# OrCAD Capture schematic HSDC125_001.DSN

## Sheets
1 P08:  TUSB3410: size B; title: TDP0604WQFNEVM, TUSB3410; rev: A.0; company: Texas Instruments, CIS/ICP; note: GAGGIA.DSN
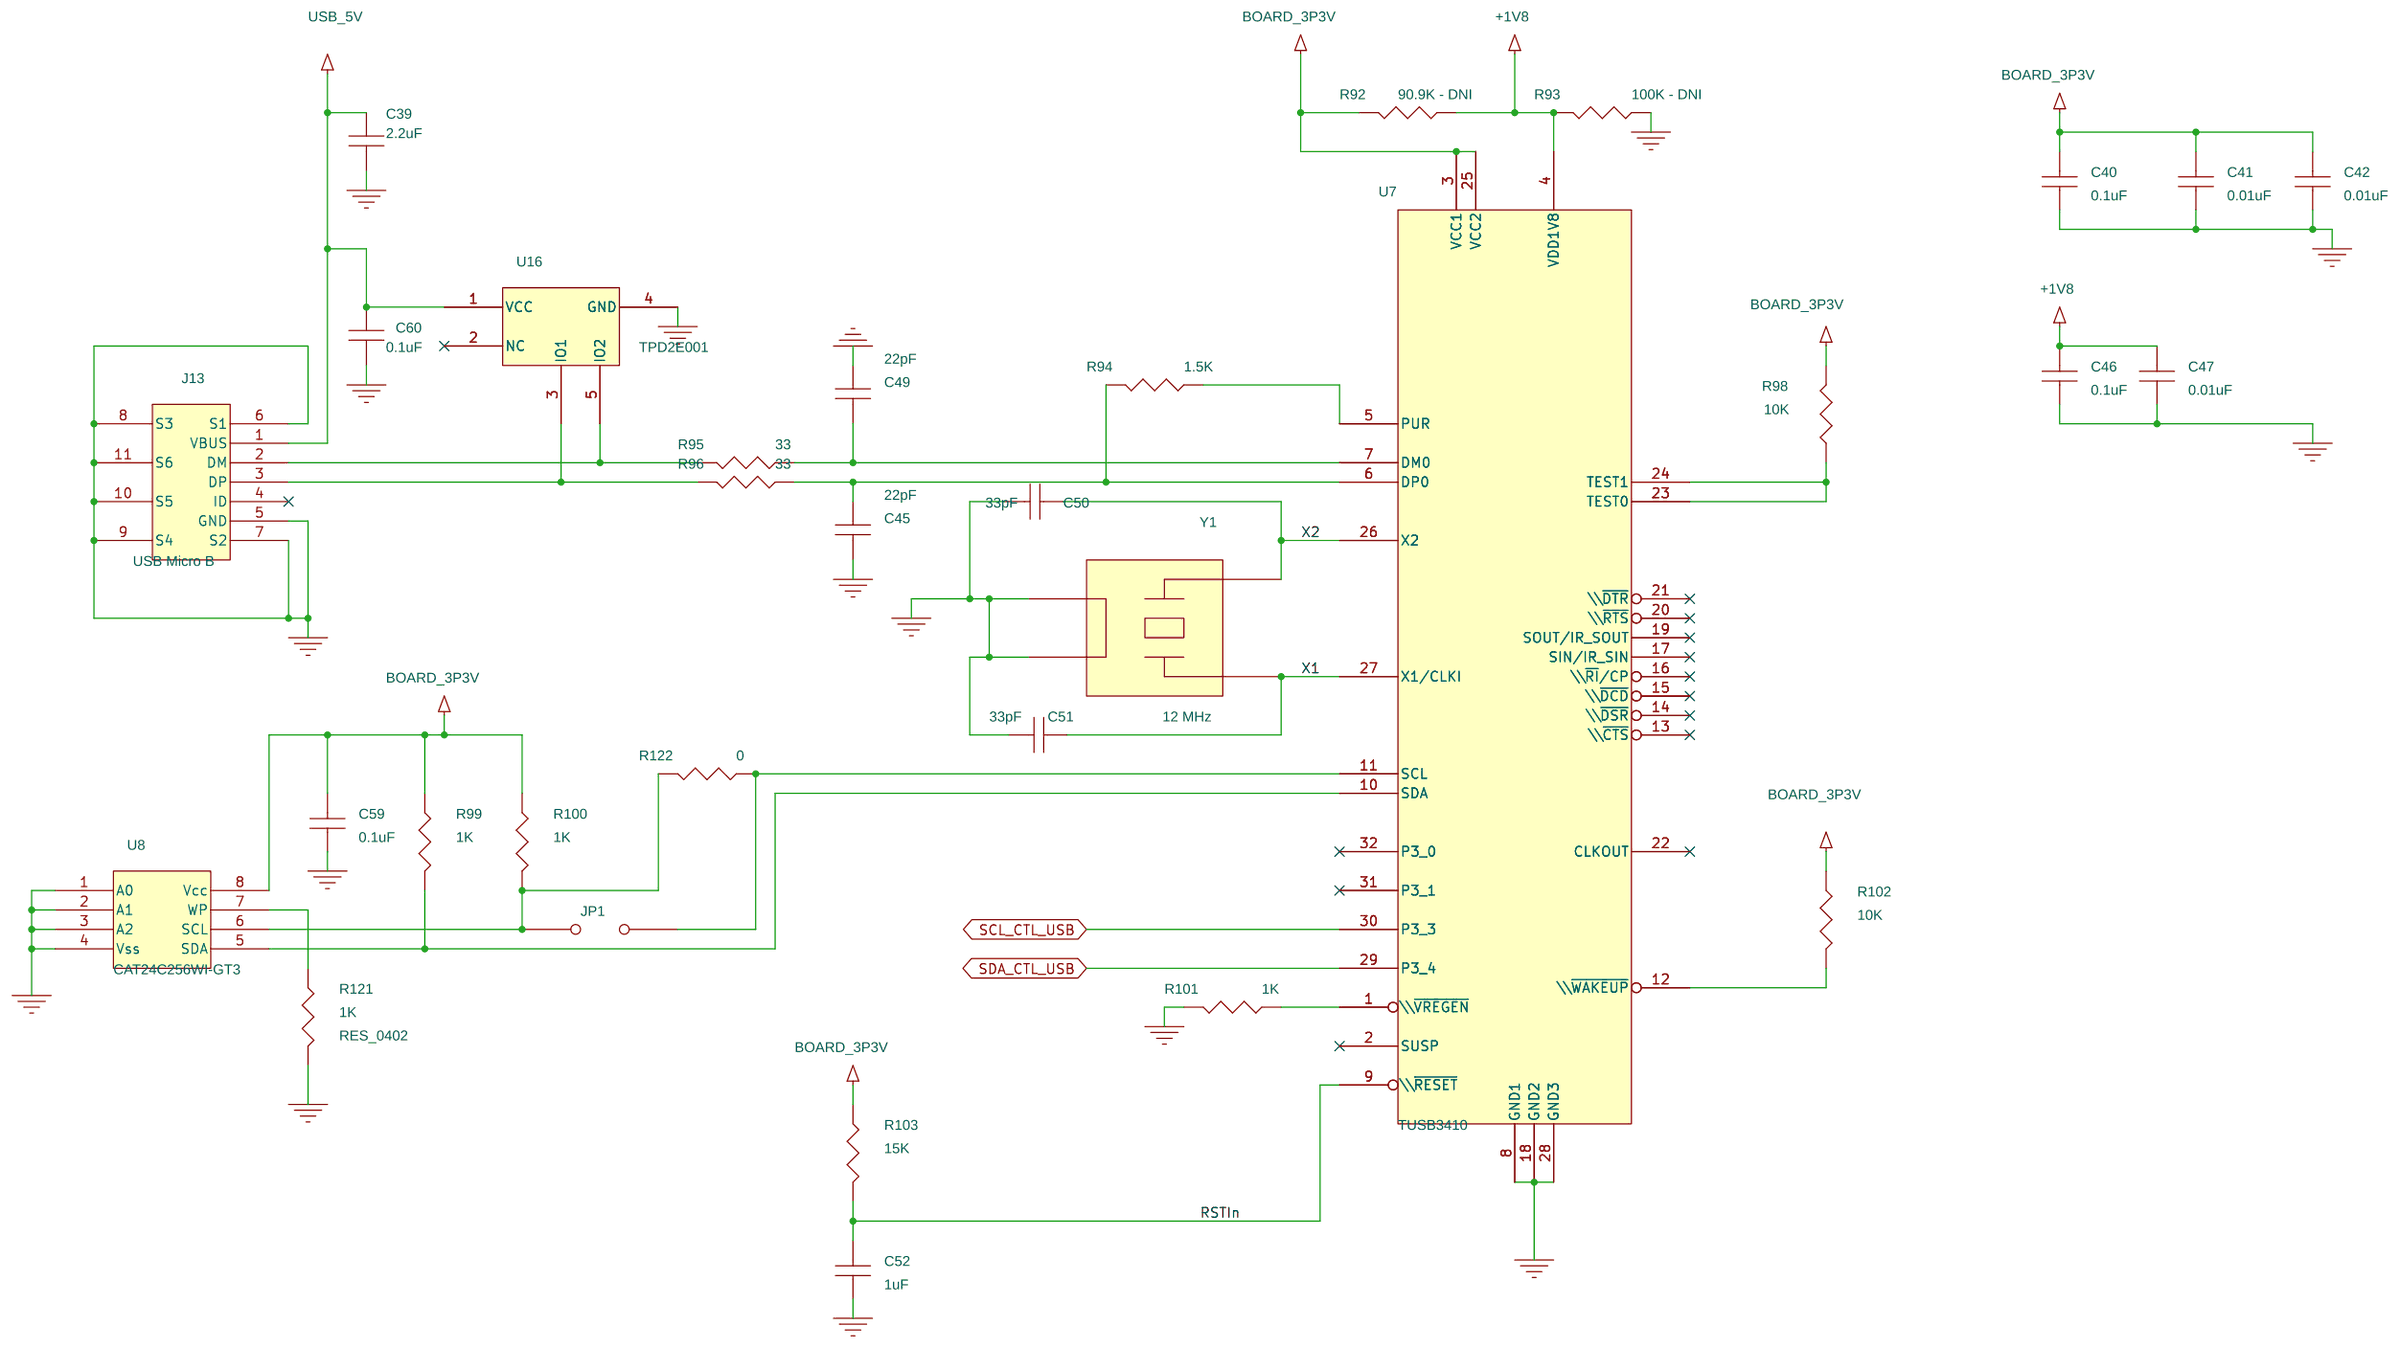
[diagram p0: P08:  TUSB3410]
2 P06:  RESET: size A; title: TDP0604WQFNEVM, RESET
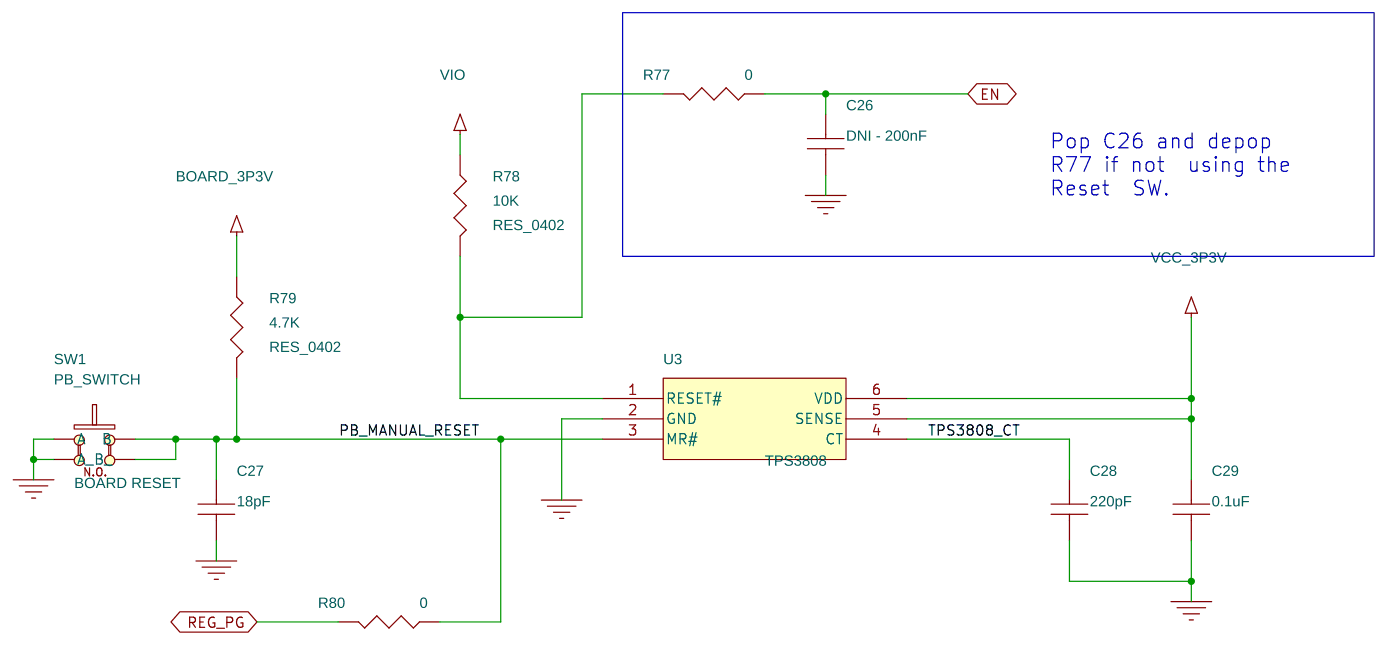
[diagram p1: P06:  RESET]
3 P01:  TITLE: title: TDP0604WQFNEVM, PROJECT# HSDC125_001
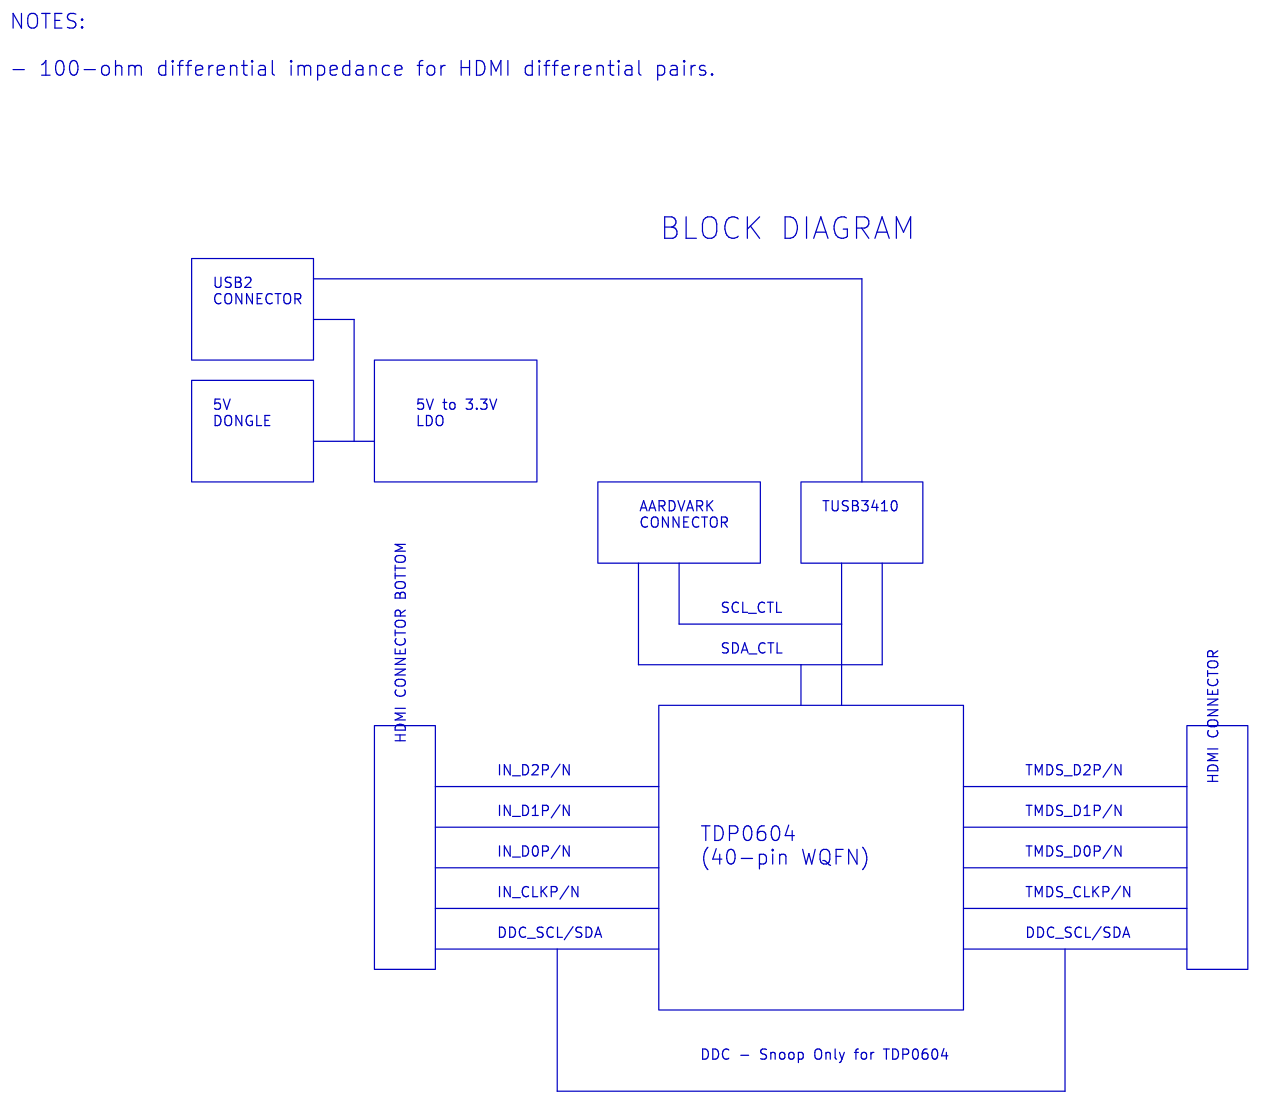
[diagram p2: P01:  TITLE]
4 P07:  POWER: size B; title: TDP0604WQFNEVM, REGULATORS
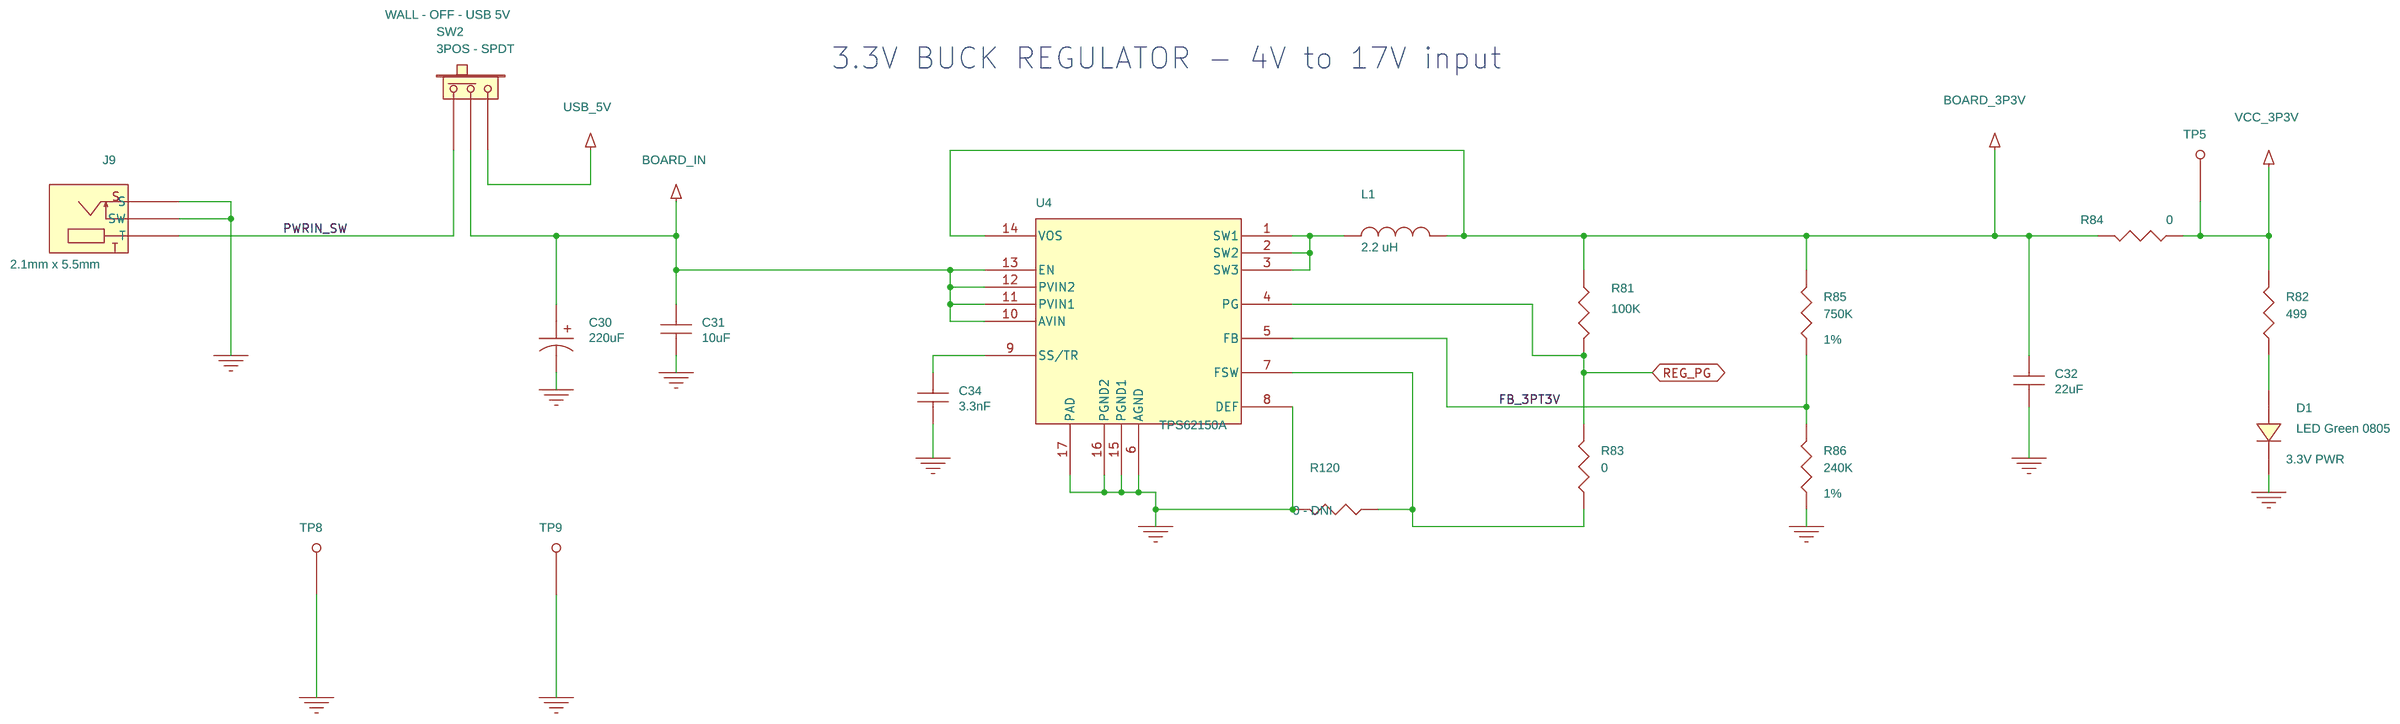
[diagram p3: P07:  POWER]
5 P03:  TDP0604WQFN: size B; title: TDP0604WQFNEVM, TDP0604 WQFN
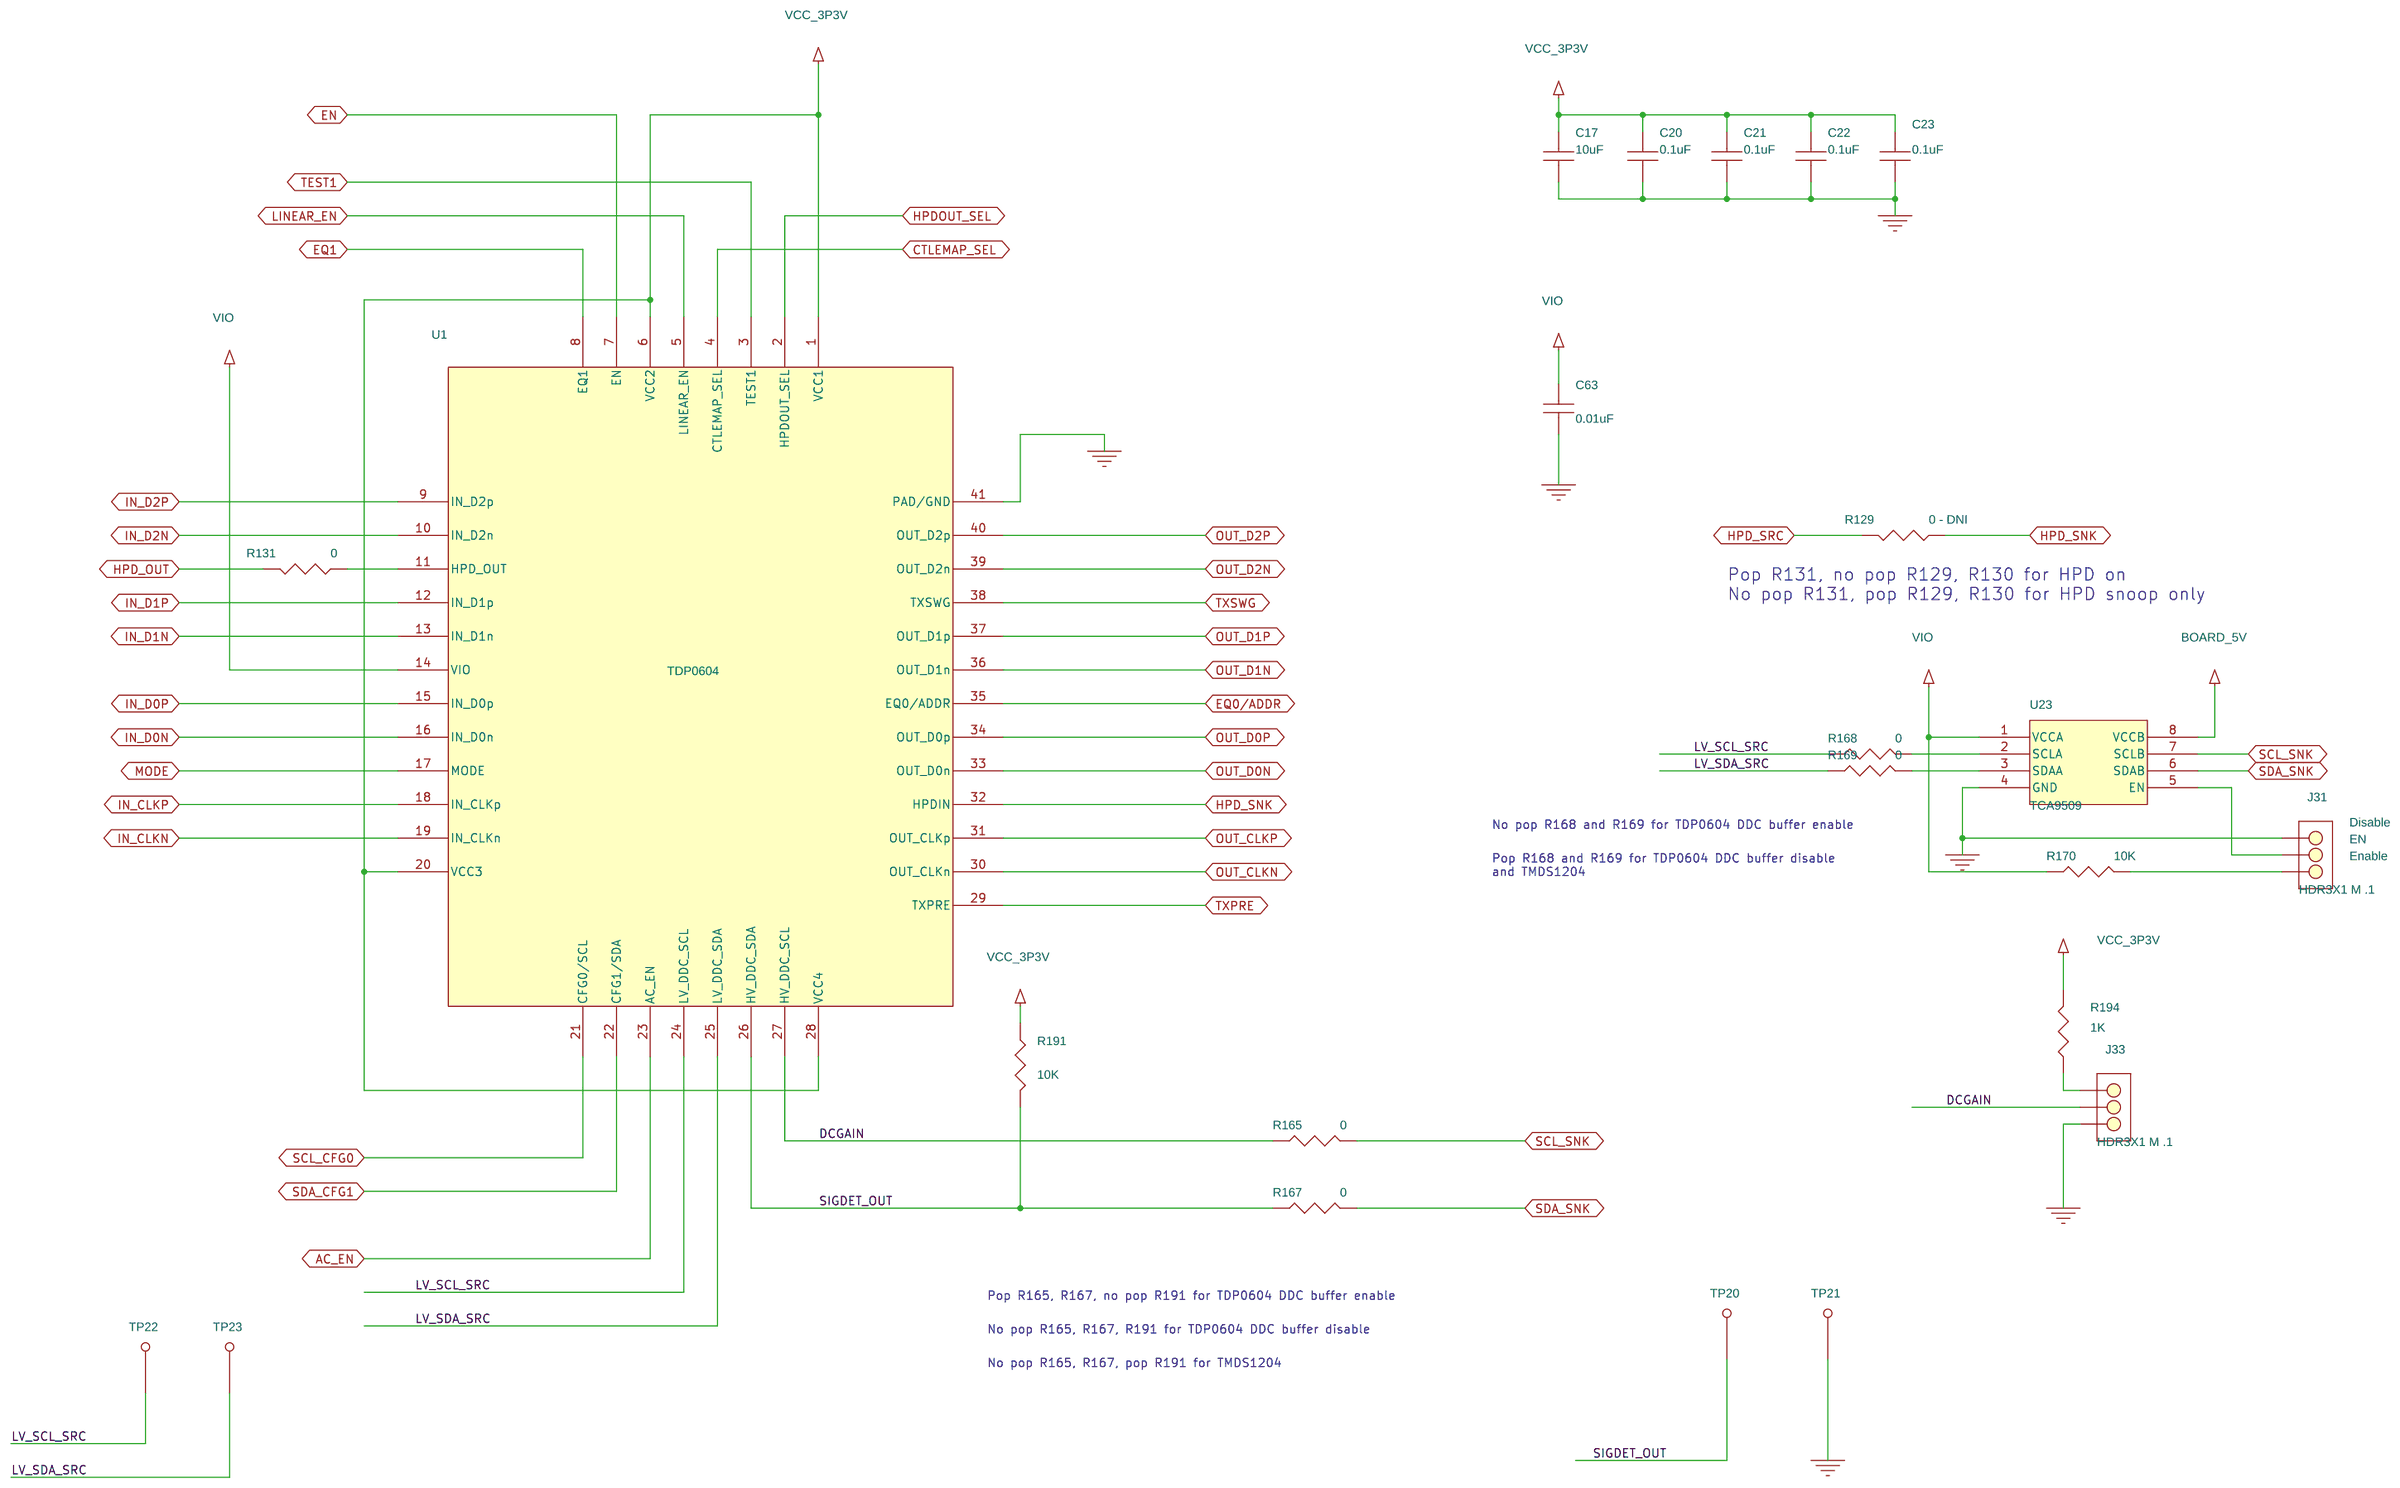
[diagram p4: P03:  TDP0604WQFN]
6 P09:  HARDWARE: title: TDP0604WQFNEVM, HARDWARE
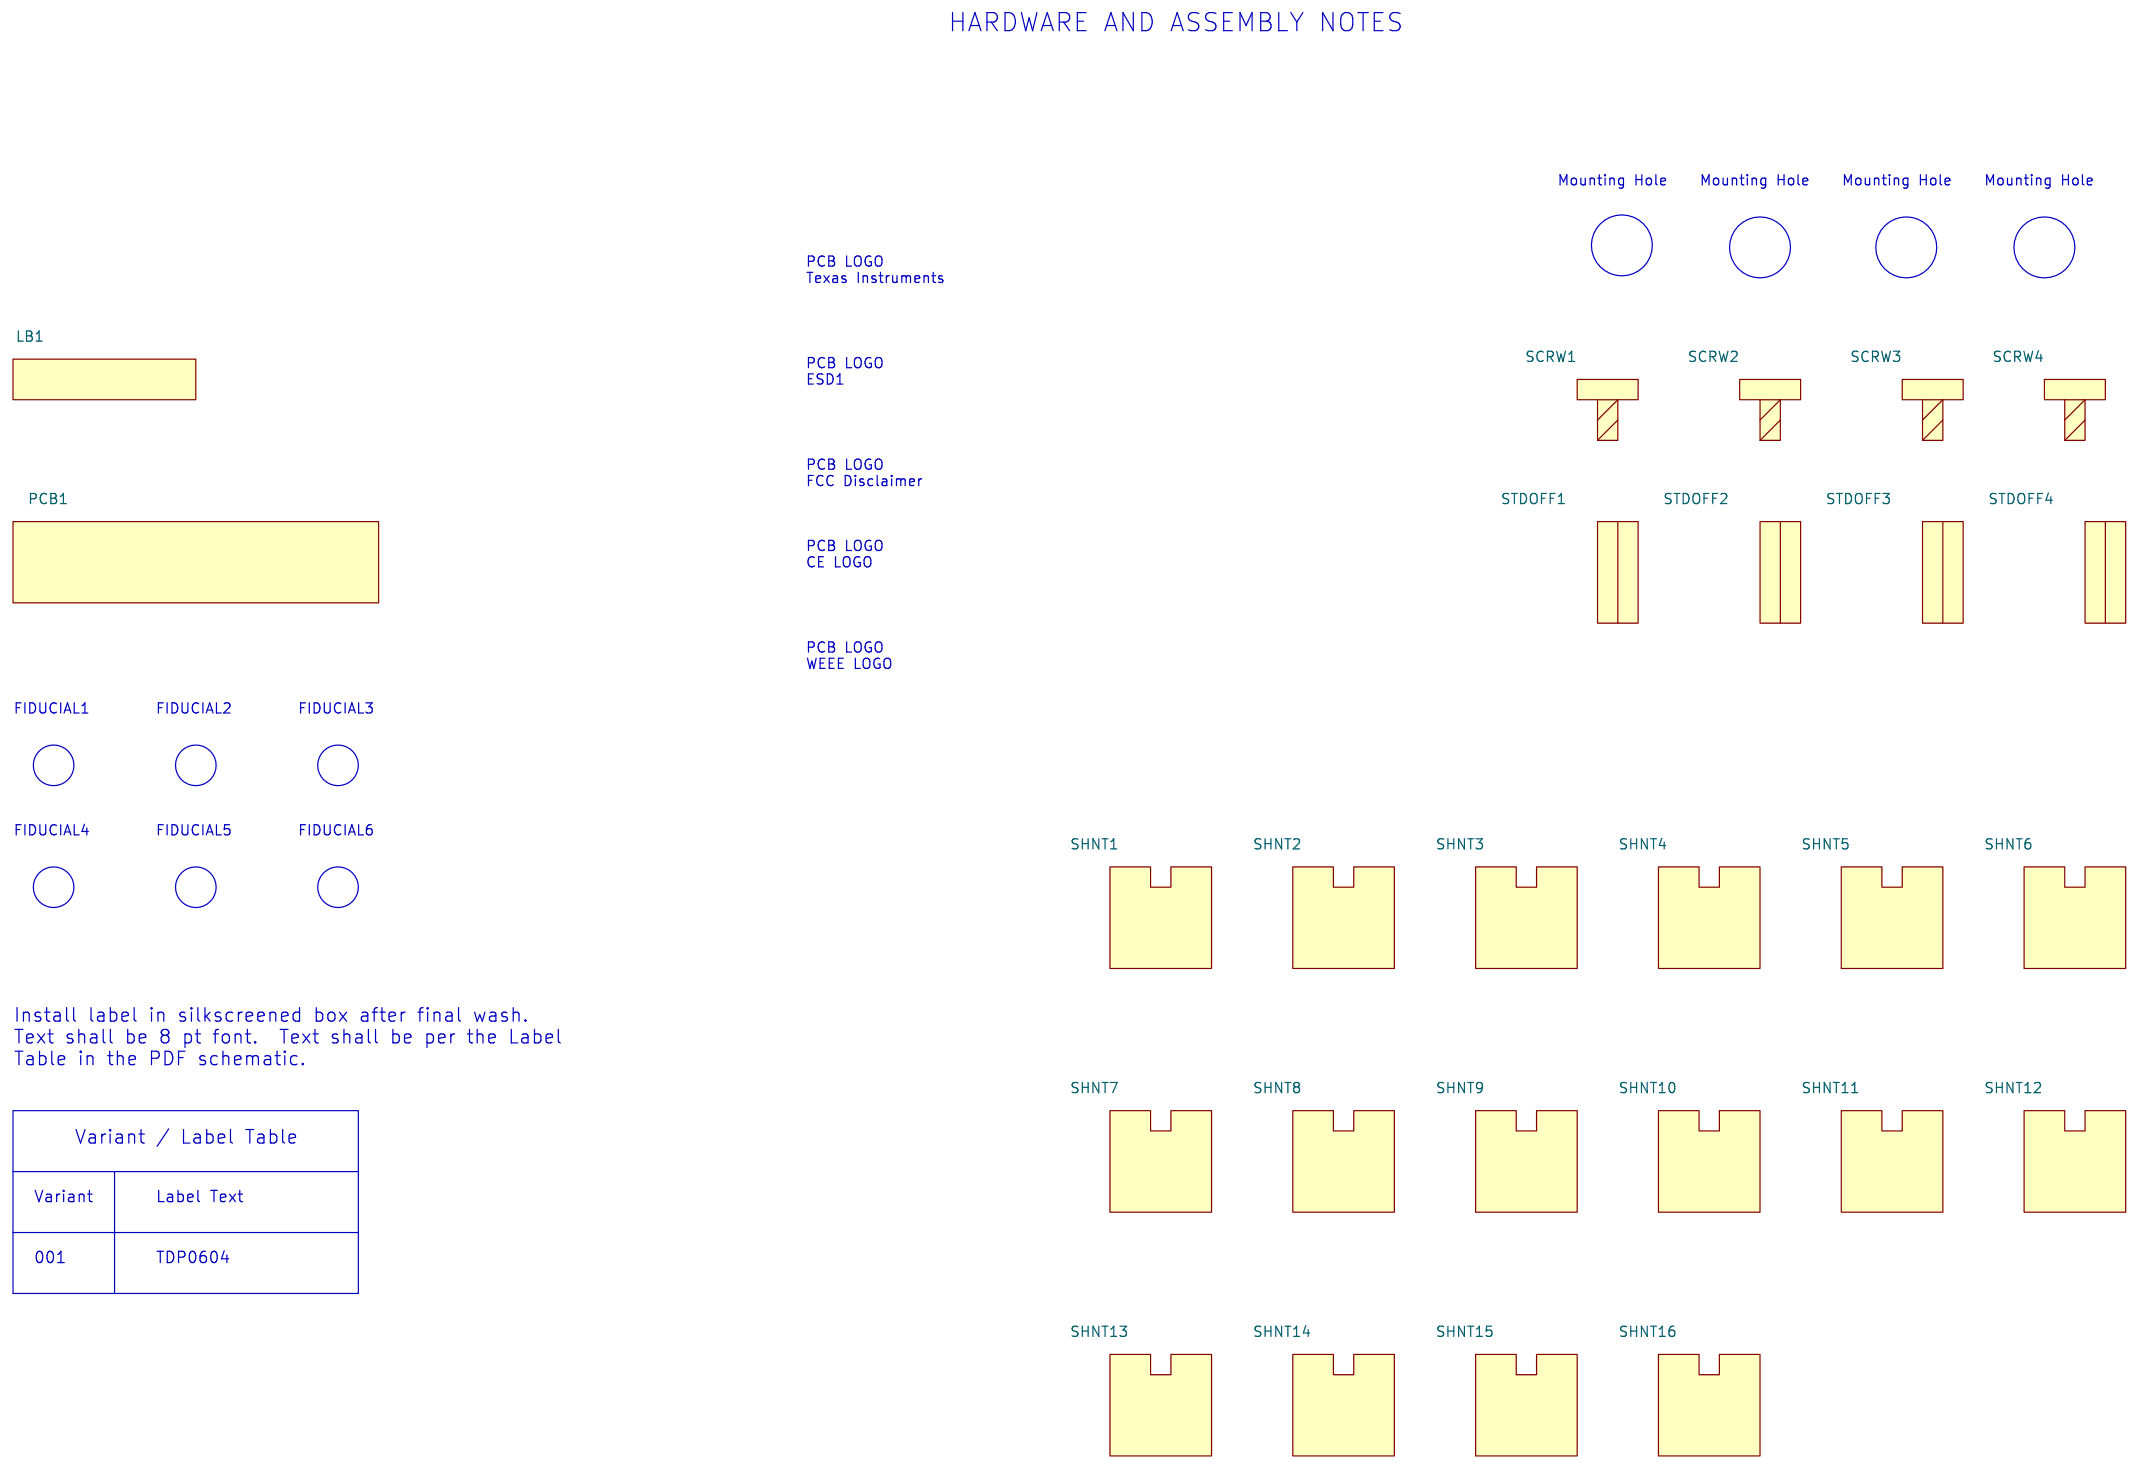
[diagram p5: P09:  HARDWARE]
7 P02:  HDMI INPUT CONNECTOR: size B; title: TDP0604WQFNEVM, HDMI INPUT
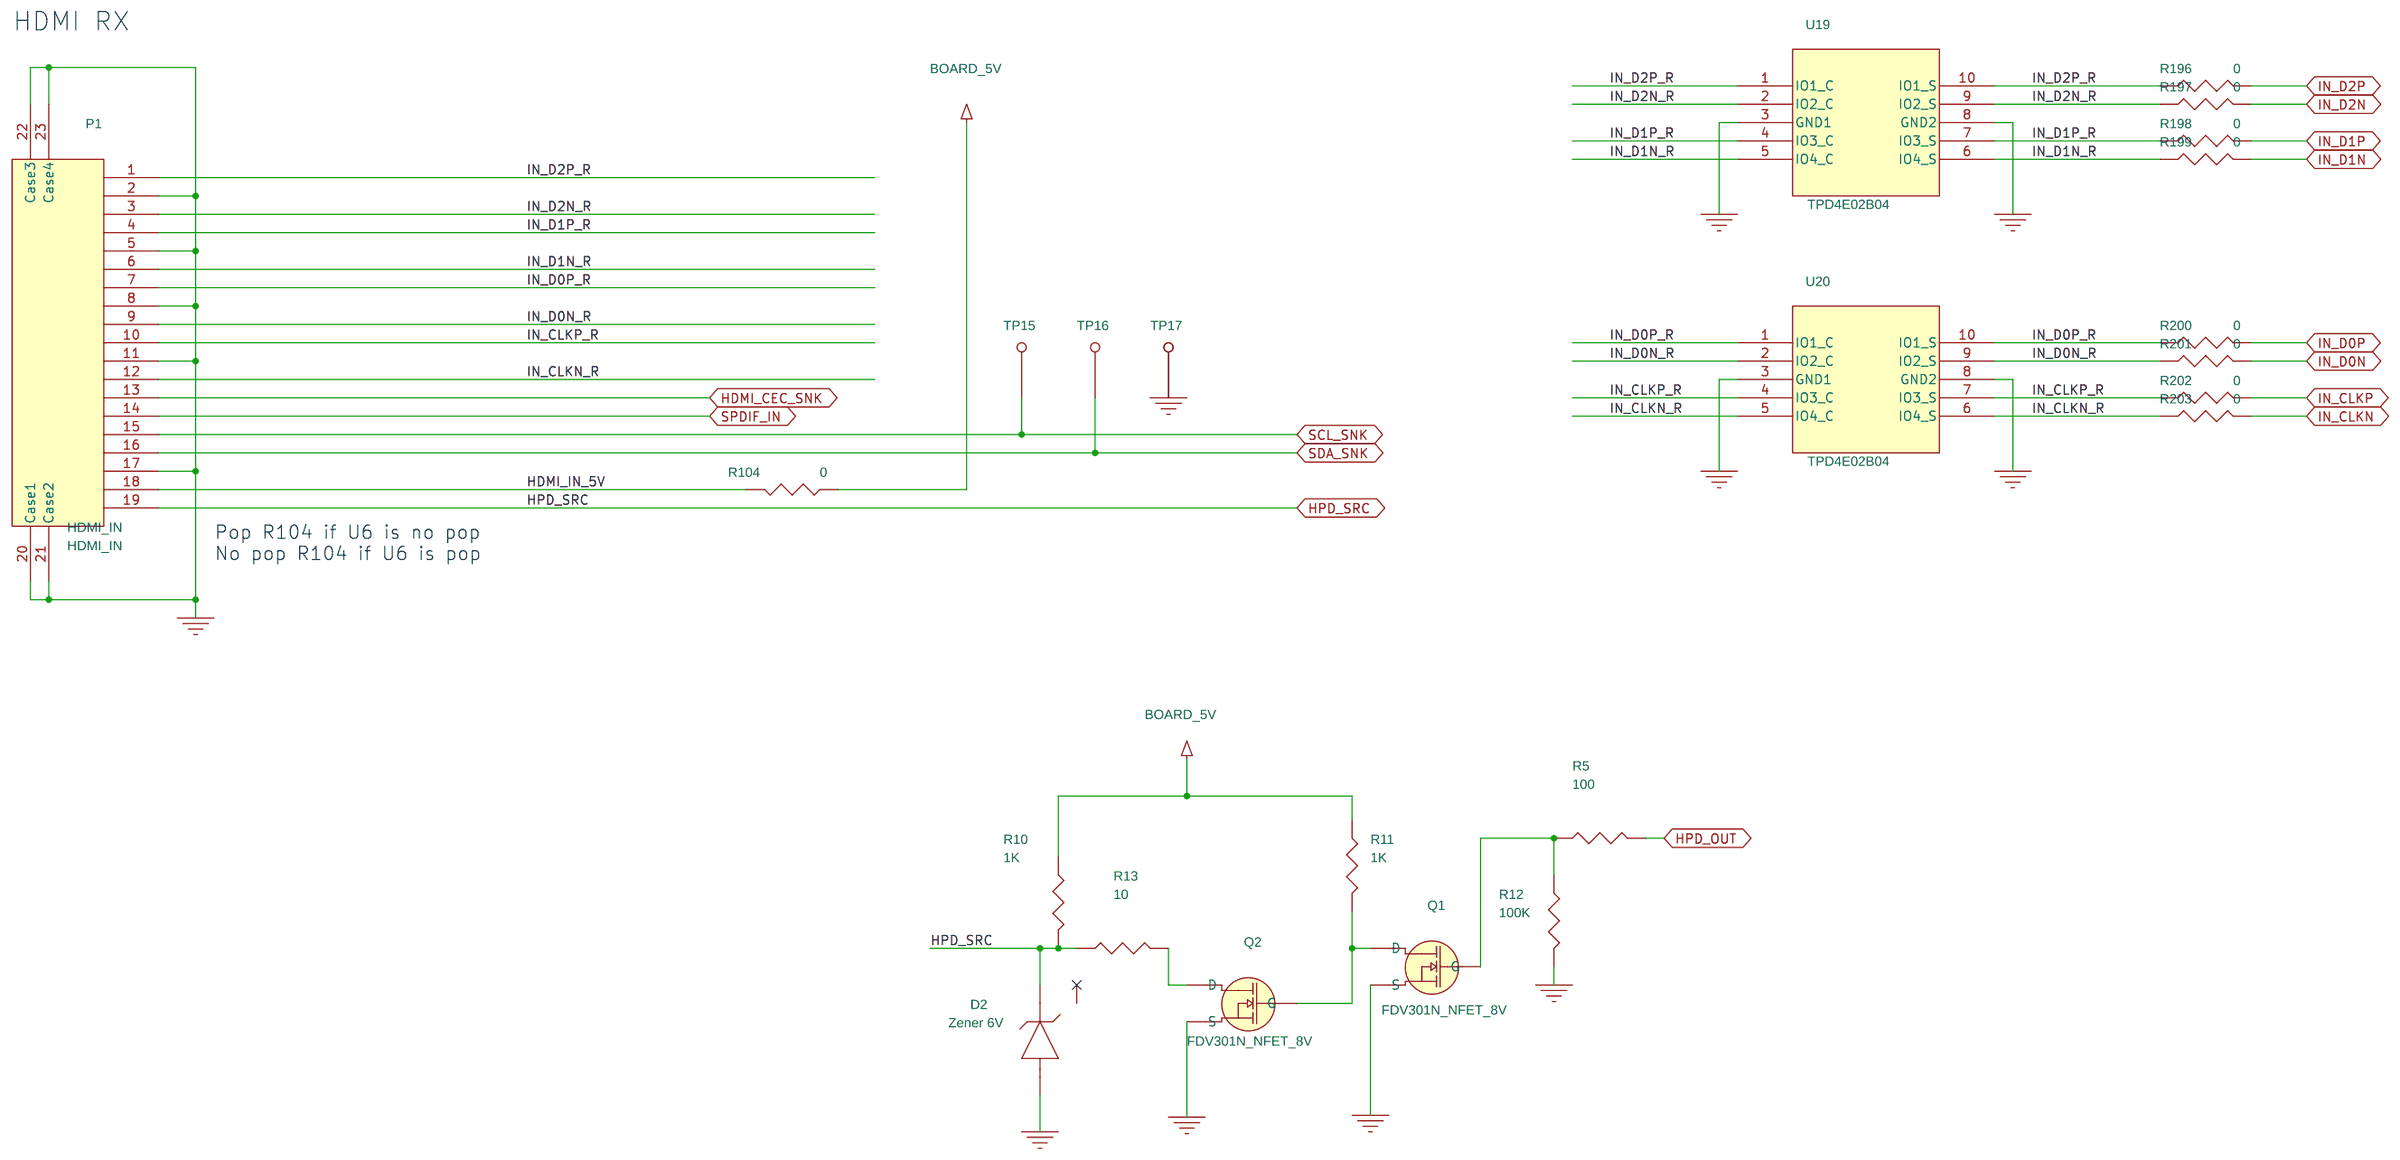
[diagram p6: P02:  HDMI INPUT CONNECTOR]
8 P04:  HDMI TX CONNECTOR: size B; title: TDP0604WQFNEVM, HDMI OUTPUT
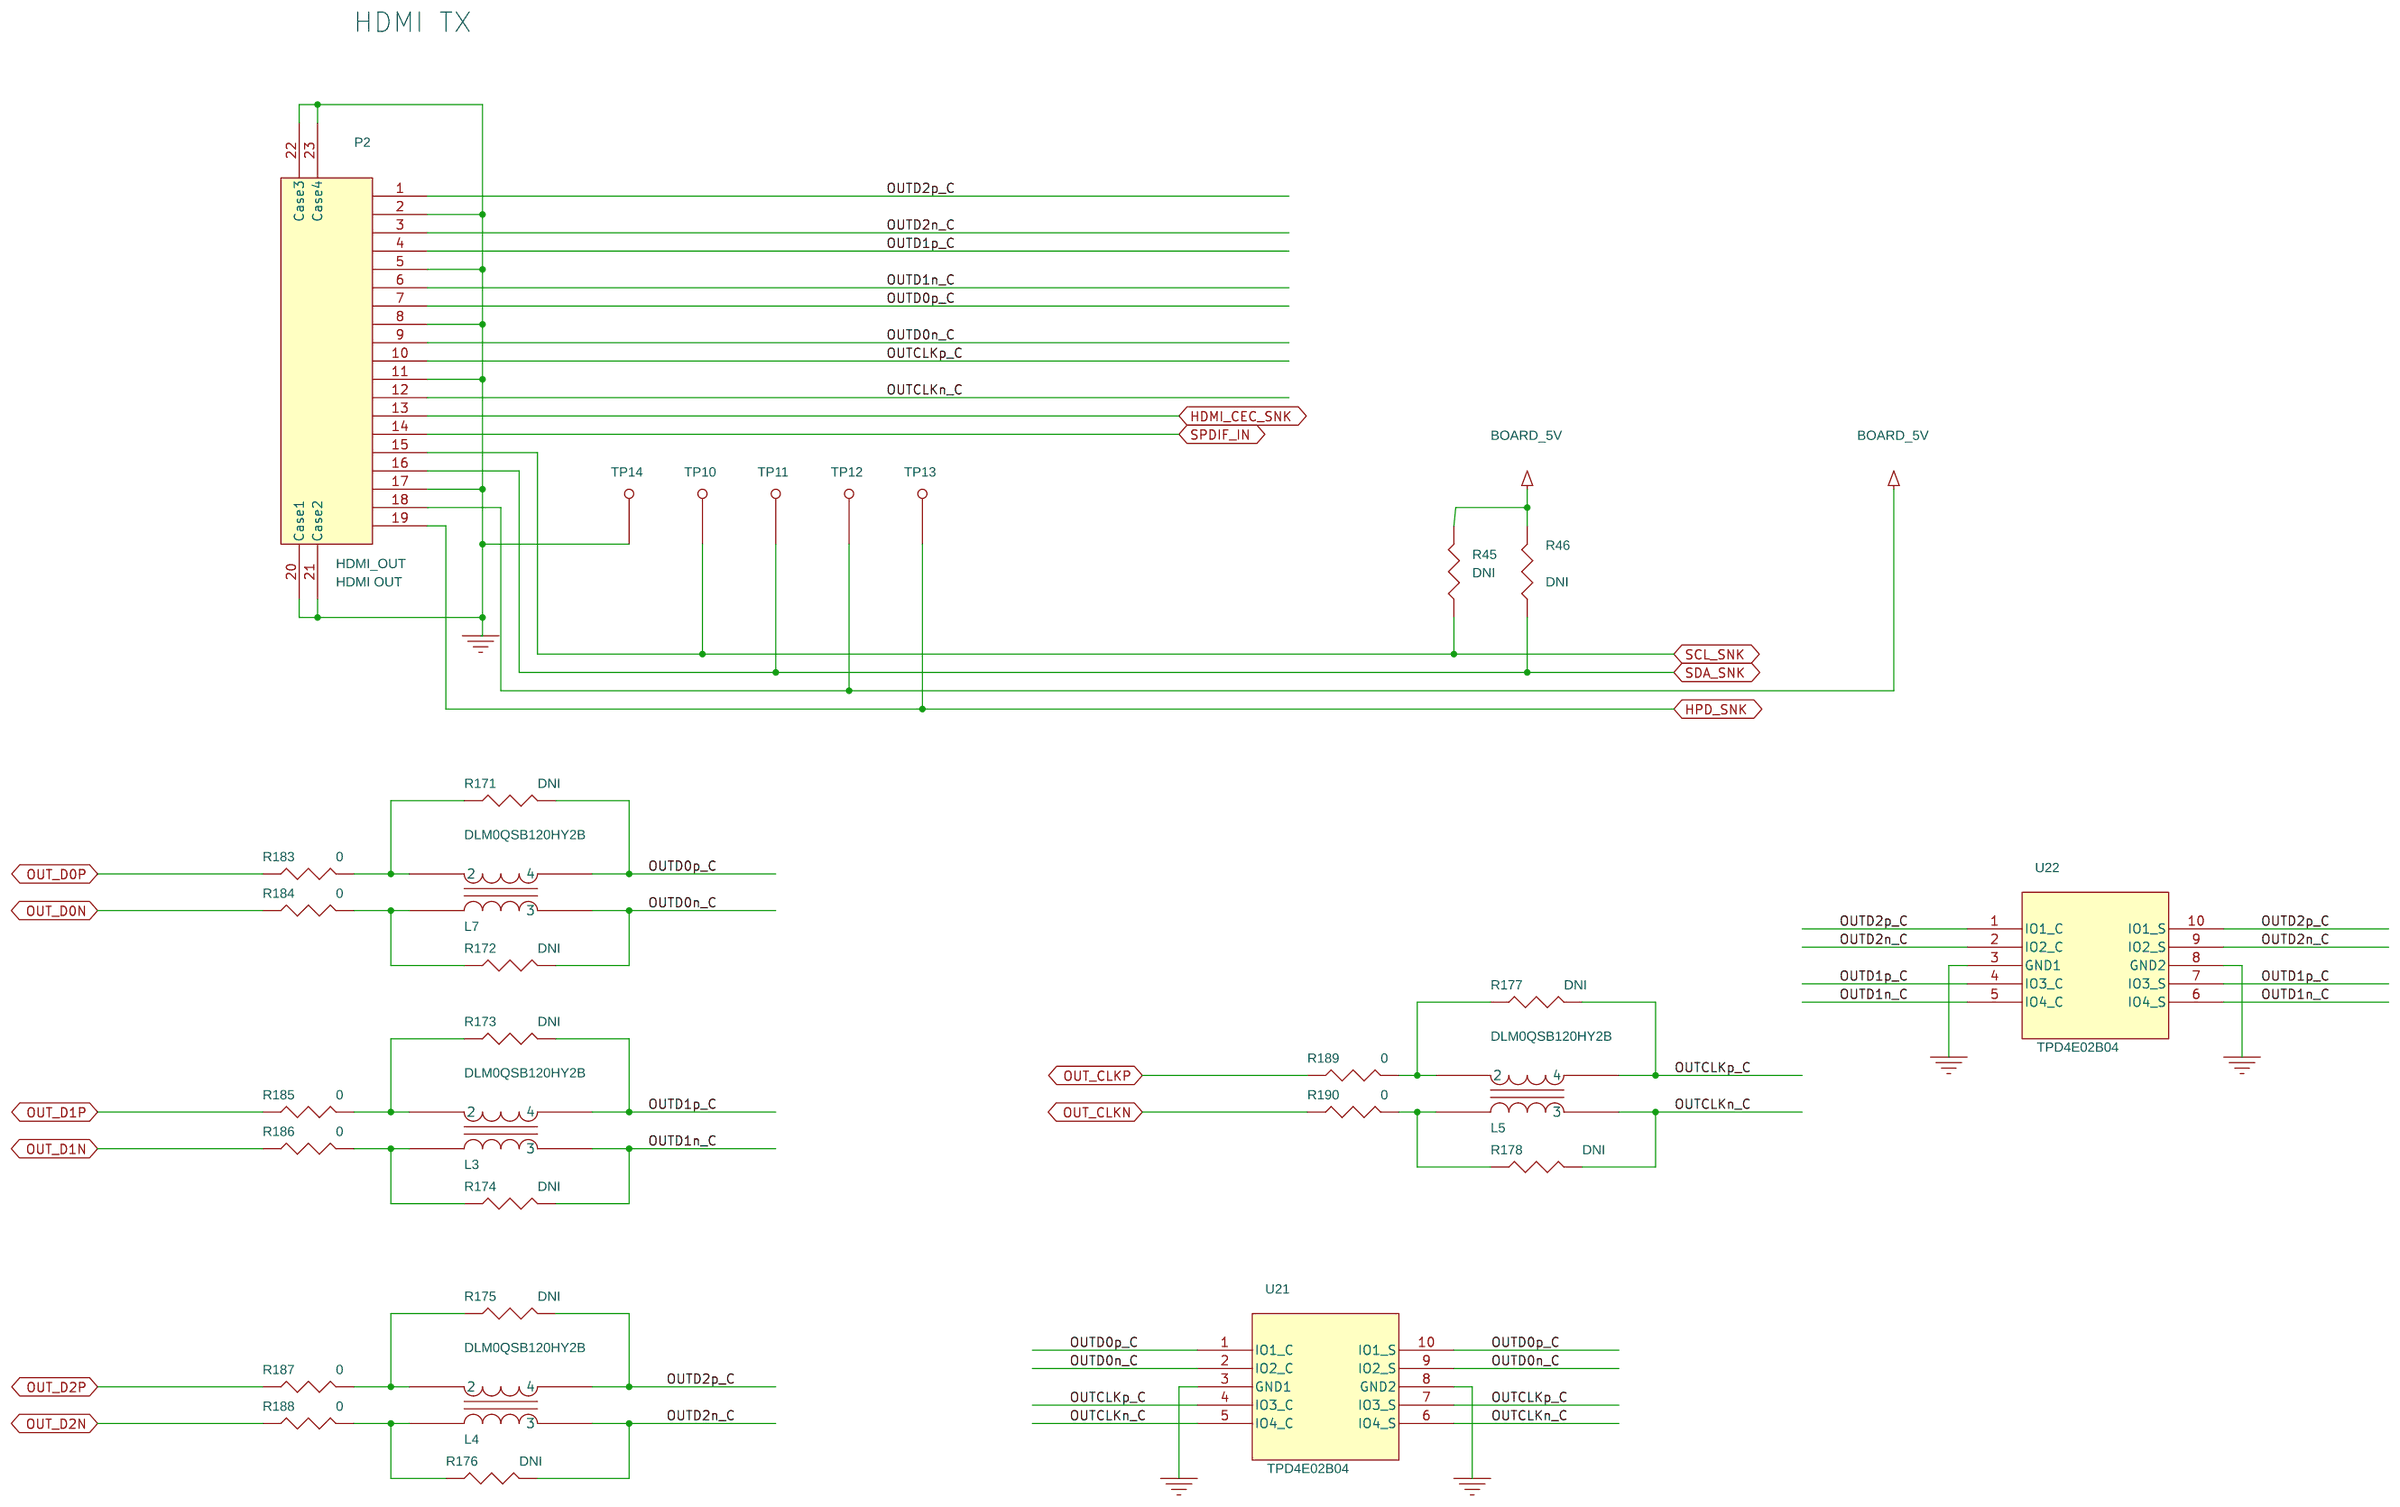
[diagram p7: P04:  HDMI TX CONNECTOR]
9 P05:  TDP0604WQFN SEL OPTIONS: size B; title: TDP0604WQFNEVM, SELECT OPTIONS
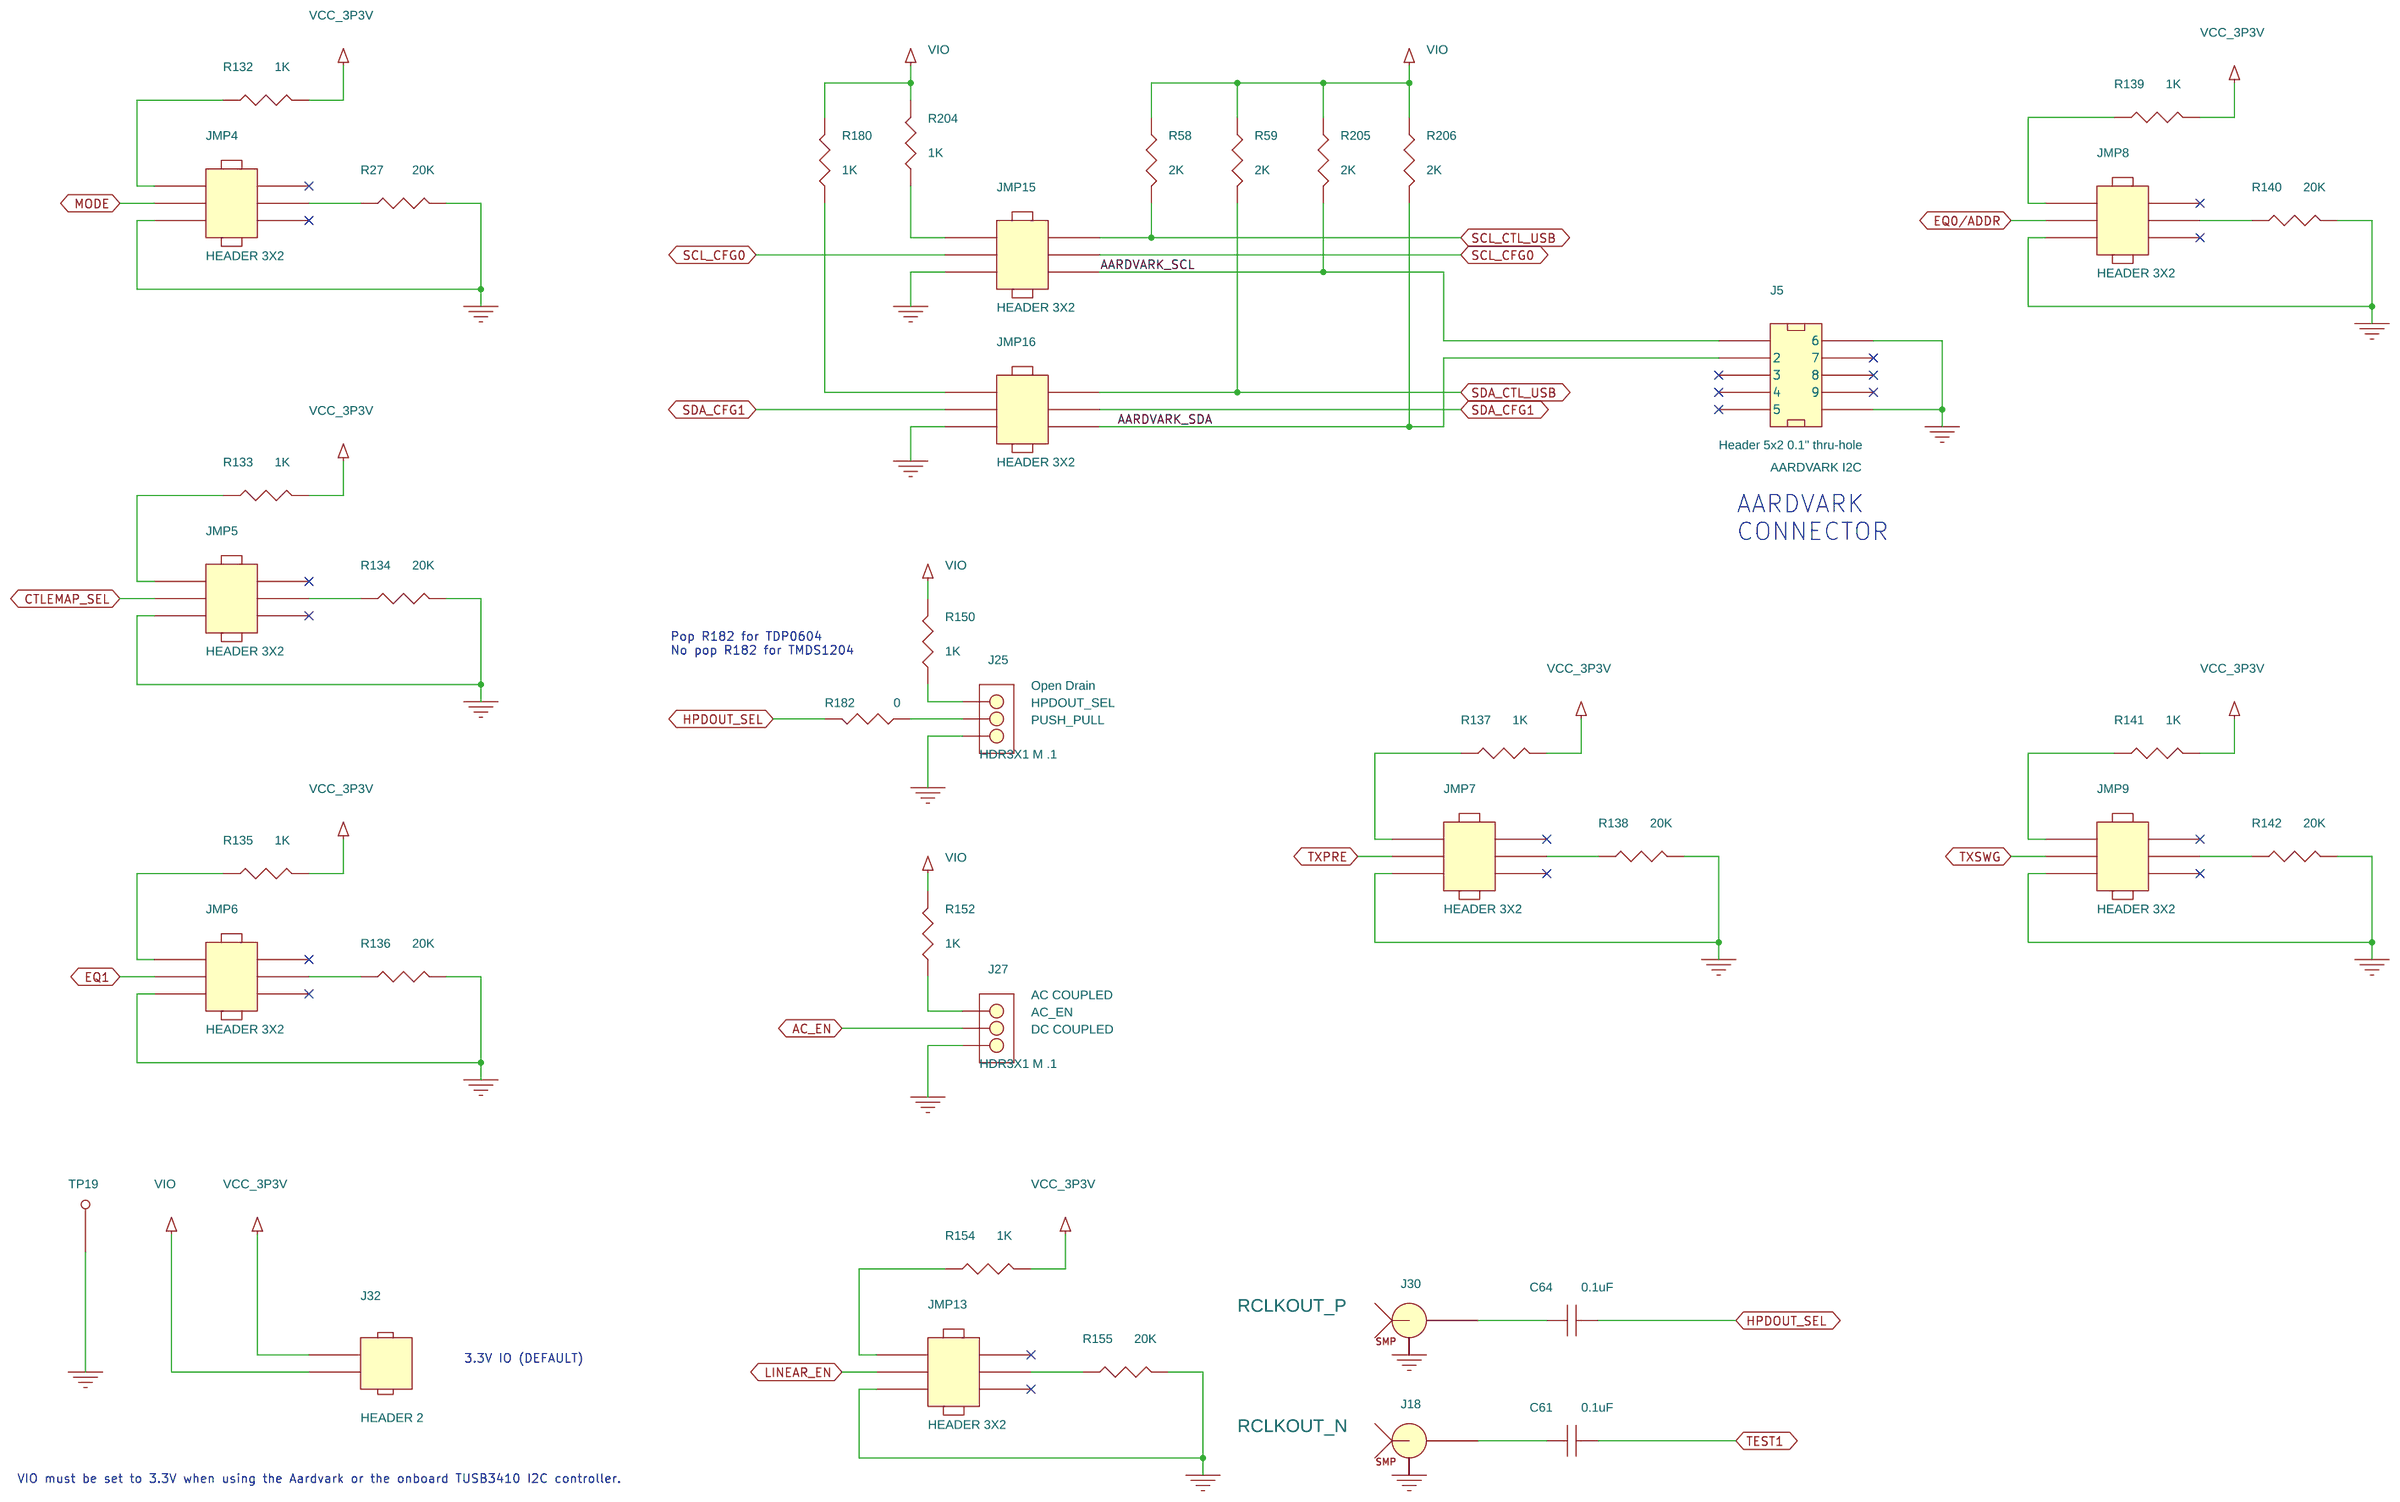
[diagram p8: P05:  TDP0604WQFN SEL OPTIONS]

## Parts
sheet P02:  HDMI INPUT CONNECTOR
D2  Zener 6V  [SOT-23_123]
P1  HDMI_IN  [HDMI_SMRT_47151-001]
Q1  FDV301N_NFET_8V  [SOT-23_123]
Q2  FDV301N_NFET_8V  [SOT-23_123]
R5  100  [RES_0402]
R10  1K  [RES_0402]
R11  1K  [RES_0402]
R12  100K  [RES_0402]
R13  10  [RES_0402]
R104  0  [RES_0402]
R196  0  [RES_0201]
R197  0  [RES_0201]
R198  0  [RES_0201]
R199  0  [RES_0201]
R200  0  [RES_0201]
R201  0  [RES_0201]
R202  0  [RES_0201]
R203  0  [RES_0201]
TP15  LP  [TP_THVT_5006]
TP16  LP  [TP_THVT_5006]
TP17  LP  [TP_THVT_5006]
U19  TPD4E02B04  [DQA0010BA]
U20  TPD4E02B04  [DQA0010BA]
sheet P03:  TDP0604WQFN
C17  10uF  [CAP_0805]
C20  0.1uF  [CAP_0402]
C21  0.1uF  [CAP_0402]
C22  0.1uF  [CAP_0402]
C23  0.1uF  [CAP_0402]
C63  0.01uF  [CAP_0402]
J31  HDR3X1 M .1  [HDR_THVT_1x3_254_1097]
J33  HDR3X1 M .1  [HDR_THVT_1x3_254_1097]
R129  0 - DNI  [RES_0201]
R131  0  [RES_0402]
R165  0  [RES_0402]
R167  0  [RES_0402]
R168  0  [RES_0402]
R169  0  [RES_0402]
R170  10K  [RES_0402]
R191  10K  [RES_0402]
R194  1K  [RES_0402]
TP20  LP  [TP_THVT_5006]
TP21  LP  [TP_THVT_5006]
TP22  LP  [TP_THVT_5006]
TP23  LP  [TP_THVT_5006]
U1  TDP0604  [SKT_IRONWOOD_C14861_SLDR]
U23  TCA9509  [DGK0008AA]
sheet P04:  HDMI TX CONNECTOR
L3  DLM0QSB120HY2B  [IND_SM_4_DLW21S_H]
L4  DLM0QSB120HY2B  [IND_SM_4_DLW21S_H]
L5  DLM0QSB120HY2B  [IND_SM_4_DLW21S_H]
L7  DLM0QSB120HY2B  [IND_SM_4_DLW21S_H]
P2  HDMI_OUT  [HDMI_SMRT_47151-001]
R45  DNI  [RES_0402]
R46  DNI  [RES_0402]
R171  DNI  [RES_0201]
R172  DNI  [RES_0201]
R173  DNI  [RES_0201]
R174  DNI  [RES_0201]
R175  DNI  [RES_0201]
R176  DNI  [RES_0201]
R177  DNI  [RES_0201]
R178  DNI  [RES_0201]
R183  0  [RES_0201]
R184  0  [RES_0201]
R185  0  [RES_0201]
R186  0  [RES_0201]
R187  0  [RES_0201]
R188  0  [RES_0201]
R189  0  [RES_0201]
R190  0  [RES_0201]
TP10  LP  [TP_THVT_5006]
TP11  LP  [TP_THVT_5006]
TP12  LP  [TP_THVT_5006]
TP13  LP  [TP_THVT_5006]
TP14  LP  [TP_THVT_5006]
U21  TPD4E02B04  [DQA0010BA]
U22  TPD4E02B04  [DQA0010BA]
sheet P05:  TDP0604WQFN SEL OPTIONS
C61  0.1uF  [CAP_0402]
C64  0.1uF  [CAP_0402]
J5  Header 5x2 0.1" thru-hole  [CON_SHRD_THVT_N2510-6002-xx]
J18  SMP  [CON_SMVT_19S101-40ML5_R04350]
J25  HDR3X1 M .1  [HDR_THVT_1x3_254_1097]
J27  HDR3X1 M .1  [HDR_THVT_1x3_254_1097]
J30  SMP  [CON_SMVT_19S101-40ML5_R04350]
J32  HEADER 2  [HDR_THVT_1X2_254_820]
JMP4  HEADER 3X2  [HDR_THVT_2x3_254_1097]
JMP5  HEADER 3X2  [HDR_THVT_2x3_254_1097]
JMP6  HEADER 3X2  [HDR_THVT_2x3_254_1097]
JMP7  HEADER 3X2  [HDR_THVT_2x3_254_1097]
JMP8  HEADER 3X2  [HDR_THVT_2x3_254_1097]
JMP9  HEADER 3X2  [HDR_THVT_2x3_254_1097]
JMP13  HEADER 3X2  [HDR_THVT_2x3_254_1097]
JMP15  HEADER 3X2  [HDR_THVT_2x3_254_1097]
JMP16  HEADER 3X2  [HDR_THVT_2x3_254_1097]
R27  20K  [RES_0402]
R58  2K  [RES_0402]
R59  2K  [RES_0402]
R132  1K  [RES_0402]
R133  1K  [RES_0402]
R134  20K  [RES_0402]
R135  1K  [RES_0402]
R136  20K  [RES_0402]
R137  1K  [RES_0402]
R138  20K  [RES_0402]
R139  1K  [RES_0402]
R140  20K  [RES_0402]
R141  1K  [RES_0402]
R142  20K  [RES_0402]
R150  1K  [RES_0402]
R152  1K  [RES_0402]
R154  1K  [RES_0402]
R155  20K  [RES_0402]
R180  1K  [RES_0402]
R182  0  [RES_0402]
R204  1K  [RES_0402]
R205  2K  [RES_0402]
R206  2K  [RES_0402]
TP19  LP  [TP_THVT_5006]
sheet P06:  RESET
C26  DNI - 200nF  [CAP_0402]
C27  18pF  [CAP_0402]
C28  220pF  [CAP_0402]
C29  0.1uF  [CAP_0402]
R77  0  [RES_0402]
R78  10K  [RES_0402]
R79  4.7K  [RES_0402]
R80  0  [RES_0402]
SW1  PB_SWITCH  [SW_SMVT_B3SN-3012]
U3  TPS3808  [DBV0006AA]
sheet P07:  POWER
C30  220uF  [TANT_7343-31]
C31  10uF  [CAP_0805]
C32  22uF  [CAP_0805]
C34  3.3nF  [CAP_0402]
D1  LED Green 0805  [LED_SM_LTST-C171]
J9  2.1mm x 5.5mm  [JACK_THRT_PJ-202AH]
L1  2.2 uH  [IND_SM_VLS252010]
R81  100K  [RES_0402]
R82  499  [RES_0201]
R83  0  [RES_0402]
R84  0  [RES_0402]
R85  750K  [RES_0402]
R86  240K  [RES_0402]
R120  0 - DNI  [RES_0201]
SW2  3POS - SPDT  [SW_SMVT_MS13ANx03]
TP5  LP  [TP_THVT_5006]
TP8  LP  [TP_THVT_5006]
TP9  LP  [TP_THVT_5006]
U4  TPS62150A  [RGT0016EA_168x168]
sheet P08:  TUSB3410
C39  2.2uF  [CAP_0805]
C40  0.1uF  [CAP_0402]
C41  0.01uF  [CAP_0402]
C42  0.01uF  [CAP_0402]
C45  22pF  [CAP_0402]
C46  0.1uF  [CAP_0402]
C47  0.01uF  [CAP_0402]
C49  22pF  [CAP_0402]
C50  33pF  [CAP_0402]
C51  33pF  [CAP_0402]
C52  1uF  [CAP_0603]
C59  0.1uF  [CAP_0402]
C60  0.1uF  [CAP_0402]
J13  USB Micro B  [USB-uB_SMRT_10103592]
JP1  JUMPER  [HDR_THVT_1X2_254_820]
R92  90.9K - DNI  [RES_0402]
R93  100K - DNI  [RES_0402]
R94  1.5K  [RES_0402]
R95  33  [RES_0201]
R96  33  [RES_0201]
R98  10K  [RES_0402]
R99  1K  [RES_0402]
R100  1K  [RES_0402]
R101  1K  [RES_0402]
R102  10K  [RES_0402]
R103  15K  [RES_0402]
R121  1K  [RES_0402]
R122  0  [RES_0402]
U7  TUSB3410  [VF0032AA]
U8  CAT24C256WI-GT3  [SOIC_8_390x490_127]
U16  TPD2E001  [DRL0005AA]
Y1  12 MHz  [XTAL_SM_4_ECX-32]
sheet P09:  HARDWARE
LB1  PCB Label 0.650"H x 0.200"W  [rectangle]
PCB1  HSDC091  [n/a]
SCRW1  NY PMS 440 005 PH  [screw]
SCRW2  NY PMS 440 005 PH  [screw]
SCRW3  NY PMS 440 005 PH  [screw]
SCRW4  NY PMS 440 005 PH  [screw]
SHNT1  QPC02SXGN-RC  [.1]
SHNT2  QPC02SXGN-RC  [.1]
SHNT3  QPC02SXGN-RC  [.1]
SHNT4  QPC02SXGN-RC  [.1]
SHNT5  QPC02SXGN-RC  [.1]
SHNT6  QPC02SXGN-RC  [.1]
SHNT7  QPC02SXGN-RC  [.1]
SHNT8  QPC02SXGN-RC  [.1]
SHNT9  QPC02SXGN-RC  [.1]
SHNT10  QPC02SXGN-RC  [.1]
SHNT11  QPC02SXGN-RC  [.1]
SHNT12  QPC02SXGN-RC  [.1]
SHNT13  QPC02SXGN-RC  [.1]
SHNT14  QPC02SXGN-RC  [.1]
SHNT15  QPC02SXGN-RC  [.1]
SHNT16  QPC02SXGN-RC  [.1]
STDOFF1  1902E  [Standoff]
STDOFF2  1902E  [Standoff]
STDOFF3  1902E  [Standoff]
STDOFF4  1902E  [Standoff]

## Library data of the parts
D2 = Zener_6V: MFG Part #: MMBZ5233B-7-F
P1 = CONN_HDMI_TYPE_A: MFG Part #: 500254-1927; Manuf: Molex; Manuf PN: 500254-1927; Manufacturer: Molex; Manufacturer Part Number: 500254-1927
Q1 Q2 = FDV301N_NFET_8V: MFG Part #: FDV301N
R5 R10-R13 = r0402
R45 R46 R77-R81 R84 R92-R96 R98-R104 R121 R122 R129 R131 = R: Tolerance: 5%
R165 R167-R178 R183-R191 R196-R203 = R
TP10-TP17 TP22 TP23 = TESTLOOP
U19-U22 = ESD224: MFG Part #: ESD224DQAR; Manufacturer: Texas Instruments
C17 C20-C23 C26-C29 C31 C32 C34 C39-C42 C45-C47 C49 C52 C59-C61 C63 C64 = CAP_NP
J31 J33 = HDR3X1_M__2.1: SILKTEXT1: Disable; SILKTEXT2: EN; SILKTEXT3: Enable
R132 R133 R135 R137 R139 R141 R150 R152 R154 R180 R182 R194 R204 = r0402: MFG Part #: ERJ-2GEJ102X; Manufacturer: Panasonic Electronic Components
TP5 TP8 TP9 TP19-TP21 = TESTLOOP: MFG Part #: 151-103-RC; Manuf: KOBIKONN; Manuf PN: 151-103-RC; Manufacturer: KOBIKONN
U1 = TUSB1044RNQ_3: MFG Part #: TUSB1044; Manufacturer: Texas Instruments
U23 = TCA9509
L3-L5 L7 = CHOKE_CM_0: MFG Part #: DLW21SN900HQ2L; Manufacturer: Murata
P2 = CONN_HDMI_TYPE_A: MFG Part #: 500254-1927; Manuf: Molex; Manuf PN: 500254-1927; Manufacturer: Molex; Manufacturer Part Number: 500254-1927; SILKTEXT: HDMI OUT
J5 = CONN_PCB_5x2-S: MFG Part #: N2510-6002-RB; Manuf: 3M; Manuf PN: N2510-6002-RB; Manufacturer: 3M; SILKTEXT: AARDVARK I2C
J18 = SMP_0: MFG Part #: 19S101-40ML5; Manufacturer Part Number: 19S101-40ML5; SILKTEXT1: RCLKOUT_N
J25 = HDR3X1_M__2.1: MFG Part #: 103321-3; Manufacturer: TE Connectivity AMP Connectors; SILKTEXT1: Open Drain; SILKTEXT2: HPDOUT_SEL; SILKTEXT3: PUSH_PULL
J27 = HDR3X1_M__2.1: MFG Part #: 103321-3; Manufacturer: TE Connectivity AMP Connectors; SILKTEXT1: AC COUPLED; SILKTEXT2: AC_EN; SILKTEXT3: DC COUPLED
J30 = SMP_0: MFG Part #: 19S101-40ML5; Manufacturer Part Number: 19S101-40ML5; SILKTEXT1: RCLKOUT_P
J32 = HEADER_2
JMP4-JMP9 JMP13 JMP15 JMP16 = HEADER_3X2: MFG Part #: 67996-106HLF; Manufacturer: AMP
R27 R134 R136 R138 R140 R142 R155 = r0402: MFG Part #: ERJ-2GEJ203X; Manufacturer: Panasonic Electronic Components
R58 R59 R82 R205 R206 = R_4: Tolerance: 5%
SW1 = PB_SWITCH_0: MFG Part #: B3SN-3012P; Manuf: OMRON; Manuf PN: B3SN-3012P; Manufacturer: OMRON; Part#: B3SN-3012P; SILKTEXT: BOARD RESET
U3 = TPS3808DBV: MFG Part #: TPS3808G30DBVT; Manuf PN: TPS3808G30DBVT; Manufacturer: Texas Instruments
C30 = CAPACITOR_POL: MFG Part #: T495X337K010ATE060; Manuf: Kemet; Manuf PN: T495X337K010ATE060; Manufacturer: Kemet
D1 = DIODE: SILKTEXT: 3.3V PWR
J9 = BNC_2: MANUF: CUI STACK; MANUF P/N: PJ-202AH; MANUF PN: PJ-202AH; MFG Part #: PJ-202AH; Manufacturer: CUI STACK; PART_NUMBER: 5V_SUPPLY; SILKTEXT: 5V ONLY!
L1 = INDUCTOR
R83 R85 R86 R120 = R: Tolerance: 1%
SW2 = SW_SLIDE_SPDT2: MFG Part #: MS13ANW03; Manuf: NKK Switches; Manuf PN: MS13ANW03; Manufacturer: NKK Switches; Manufacturer's Part Number: MS13ANW03; Part_Type: Switch\Slide; SILKTEXT: WALL - OFF - USB 5V
U4 = TPS62150A_2: Manufacturer: Texas Instruments
C50 C51 = CAP_NP: Vendor: Digi-Key
J13 = USB_Mini_AB_1: PN: 10103592-0001LF; TYPE: MOLEX MICRO AB
JP1 = JUMPER
U7 = TUSB3410_3: Manufacturer: Texas Instruments; Vendor: T.I.
U8 = I2C_0: Manufacturer: ON Semiconductor; Vendor: Digi-Key
U16 = TPD2E001-Q1: Manufacturer: Texas Instruments
Y1 = CRYSTAL14_0
LB1 = Label: Digikey: n/a; MFG Part #: THT-14-423-10; Manufacturer: Brady; Manufacturer Part Number: THT-14-423-10
PCB1 = PCB: MFG Part #: HSDC042; Manufacturer: Any; Manufacturer Part Number: HSDC042
SCRW1-SCRW4 = Screw_40x.5_Nylon: Digikey: H546-ND; Manufacturer: B&F Fastener
SHNT1-SHNT16 = Shunt: Digikey: S9337-ND; Manufacturer: Sullins
STDOFF1-STDOFF4 = Standoff: Digikey: 36-1902E-ND; Manufacturer: Keystone

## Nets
+1V8: C46.2 C47.2 R92.1 R93.2 U7.4(VDD1V8)
GND: C17.2 C20.2 C21.2 C22.2 C23.2 C26.2 C27.2 C28.2 C29.2 C30.2 C31.2 C32.2 C34.2 C39.2 C40.1 C41.1 C42.1 C45.2 C46.1 C47.1 C49.1 C50.2 C51.2 C52.1 C59.1 C60.2 C63.2 D1.2(K) D2.1 J5.2(6) J5.10 J9.2(S) J9.3(SW) J13.5(GND) J13.6(S1) J13.7(S2) J13.8(S3) J13.9(S4) J13.10(S5) J13.11(S6) J18.2 J18.3 J18.4 J18.5 J18.6 J18.7 J18.8 J18.9 J18.10 J25.3 J27.3 J30.2 J30.3 J30.4 J30.5 J30.6 J30.7 J30.8 J30.9 J30.10 J31.1 J33.3 JMP4.6 JMP5.6 JMP6.6 JMP7.6 JMP8.6 JMP9.6 JMP13.6 JMP15.6 JMP16.6 P1.2 P1.5 P1.8 P1.11 P1.17 P1.20(Case1) P1.21(Case2) P1.22(Case3) P1.23(Case4) P2.2 P2.5 P2.8 P2.11 P2.17 P2.20(Case1) P2.21(Case2) P2.22(Case3) P2.23(Case4) Q1.2(S) Q2.2(S) R12.1 R27.2 R86.1 R93.1 R101.2 R120.2 R121.2 R134.2 R136.2 R138.2 R140.2 R142.2 R155.2 SW1.1(A) SW1.2(A_) TP8.1 TP9.1 TP14.1 TP17.1 TP19.1 TP21.1 U1.41(PAD/GND) U3.2(GND) U4.6(AGND) U4.8(DEF) U4.15(PGND1) U4.16(PGND2) U4.17(PAD) U7.8(GND1) U7.18(GND2) U7.28(GND3) U8.1(A0) U8.2(A1) U8.3(A2) U8.4(Vss) U16.4(GND) U19.3(GND1) U19.8(GND2) U20.3(GND1) U20.8(GND2) U21.3(GND1) U21.8(GND2) U22.3(GND1) U22.8(GND2) U23.4(GND) Y1.2 Y1.4
VCC_3P3V: C17.1 C20.1 C21.1 C22.1 C23.1 C29.1 J32.2 R82.2 R84.1 R132.2 R133.2 R135.2 R137.2 R139.2 R141.2 R154.2 R191.1 R194.2 TP5.1 U1.1(VCC1) U1.6(VCC2) U1.20(VCC3) U1.28(VCC4) U3.5(SENSE) U3.6(VDD)
AARDVARK_SCL: J5.1 JMP15.5 R205.2
AARDVARK_SDA: J5.3(2) JMP16.5 R206.2
AC_EN: J27.2 U1.23(AC_EN)
BOARD_3P3V: C32.1 C40.2 C41.2 C42.2 C59.2 L1.2 R79.1 R81.1 R84.2 R85.2 R92.2 R98.1 R99.1 R100.1 R102.1 R103.1 U4.14(VOS) U7.3(VCC1) U7.25(VCC2) U8.8(Vcc)
BOARD_5V: P2.18 R10.2 R11.2 R45.2 R46.1 R104.1 TP12.1 U23.8(VCCB)
BOARD_IN: C30.1 C31.1 SW2.2 U4.10(AVIN) U4.11(PVIN1) U4.12(PVIN2) U4.13(EN)
CTLEMAP_SEL: JMP5.4 U1.4(CTLEMAP_SEL)
DCGAIN: J33.2 R165.1 U1.27(HV_DDC_SCL)
EN: C26.1 R77.1 U1.7(EN)
EQ0/ADDR: JMP8.4 U1.35(EQ0/ADDR)
EQ1: JMP6.4 U1.8(EQ1)
FB_3PT3V: R85.1 R86.2 U4.5(FB)
HDMI_CEC_SNK: P1.13 P2.13
HDMI_IN_5V: P1.18 R104.2
HPD_OUT: R5.1 R131.2
HPD_SNK: P2.19 R129.1 TP13.1 U1.32(HPDIN)
HPD_SRC: D2.3 P1.19 R10.1 R13.2 R129.2
HPDOUT_SEL: C64.2 R182.2 U1.2(HPDOUT_SEL)
IN_CLKN: R203.2 U1.19(IN_CLKn)
IN_CLKN_R: P1.12 R203.1 U20.5(IO4_C) U20.6(IO4_S)
IN_CLKP: R202.2 U1.18(IN_CLKp)
IN_CLKP_R: P1.10 R202.1 U20.4(IO3_C) U20.7(IO3_S)
IN_D0N: R201.2 U1.16(IN_D0n)
IN_D0N_R: P1.9 R201.1 U20.2(IO2_C) U20.9(IO2_S)
IN_D0P: R200.2 U1.15(IN_D0p)
IN_D0P_R: P1.7 R200.1 U20.1(IO1_C) U20.10(IO1_S)
IN_D1N: R199.2 U1.13(IN_D1n)
IN_D1N_R: P1.6 R199.1 U19.5(IO4_C) U19.6(IO4_S)
IN_D1P: R198.2 U1.12(IN_D1p)
IN_D1P_R: P1.4 R198.1 U19.4(IO3_C) U19.7(IO3_S)
IN_D2N: R197.2 U1.10(IN_D2n)
IN_D2N_R: P1.3 R197.1 U19.2(IO2_C) U19.9(IO2_S)
IN_D2P: R196.2 U1.9(IN_D2p)
IN_D2P_R: P1.1 R196.1 U19.1(IO1_C) U19.10(IO1_S)
LINEAR_EN: JMP13.4 U1.5(LINEAR_EN)
LV_SCL_SRC: R168.1 TP22.1 U1.24(LV_DDC_SCL)
LV_SDA_SRC: R169.1 TP23.1 U1.25(LV_DDC_SDA)
MODE: JMP4.4 U1.17(MODE)
OUT_CLKN: R190.1 U1.30(OUT_CLKn)
OUT_CLKP: R189.1 U1.31(OUT_CLKp)
OUT_D0N: R184.1 U1.33(OUT_D0n)
OUT_D0P: R183.1 U1.34(OUT_D0p)
OUT_D1N: R186.1 U1.36(OUT_D1n)
OUT_D1P: R185.1 U1.37(OUT_D1p)
OUT_D2N: R188.1 U1.39(OUT_D2n)
OUT_D2P: R187.1 U1.40(OUT_D2p)
OUTCLKn_C: L5.2(3) P2.12 R178.2 U21.5(IO4_C) U21.6(IO4_S)
OUTCLKp_C: L5.3(4) P2.10 R177.2 U21.4(IO3_C) U21.7(IO3_S)
OUTD0n_C: L7.2(3) P2.9 R172.2 U21.2(IO2_C) U21.9(IO2_S)
OUTD0p_C: L7.3(4) P2.7 R171.2 U21.1(IO1_C) U21.10(IO1_S)
OUTD1n_C: L3.2(3) P2.6 R174.2 U22.5(IO4_C) U22.6(IO4_S)
OUTD1p_C: L3.3(4) P2.4 R173.2 U22.4(IO3_C) U22.7(IO3_S)
OUTD2n_C: L4.2(3) P2.3 R176.2 U22.2(IO2_C) U22.9(IO2_S)
OUTD2p_C: L4.3(4) P2.1 R175.2 U22.1(IO1_C) U22.10(IO1_S)
PB_MANUAL_RESET: C27.1 R79.2 R80.1 SW1.3(B_) SW1.4(B) U3.3(MR#)
PWRIN_SW: J9.1(T) SW2.1
REG_PG: R80.2 R81.2 R83.2 U4.4(PG)
RSTIn: C52.2 R103.2 U7.9(\\~{RESET})
SCL_CFG0: JMP15.3 JMP15.4 U1.21(CFG0/SCL)
SCL_CTL_USB: JMP15.1 R58.2 U7.30(P3_3)
SCL_SNK: P1.15 P2.15 R45.1 R165.2 TP10.1 TP15.1 U23.7(SCLB)
SDA_CFG1: JMP16.3 JMP16.4 U1.22(CFG1/SDA)
SDA_CTL_USB: JMP16.1 R59.2 U7.29(P3_4)
SDA_SNK: P1.16 P2.16 R46.2 R167.2 TP11.1 TP16.1 U23.6(SDAB)
SIGDET_OUT: R167.1 R191.2 TP20.1 U1.26(HV_DDC_SDA)
SPDIF_IN: P1.14 P2.14
TEST1: C61.2 U1.3(TEST1)
TPS3808_CT: C28.1 U3.4(CT)
TXPRE: JMP7.4 U1.29(TXPRE)
TXSWG: JMP9.4 U1.38(TXSWG)
USB_5V: C39.1 C60.1 J13.1(VBUS) SW2.3 U16.1(VCC)
VIO: C63.1 J32.1 R58.1 R59.1 R78.1 R150.2 R152.2 R170.1 R180.2 R204.2 R205.1 R206.1 U1.14(VIO) U23.1(VCCA)
X1: C51.1 U7.27(X1/CLKI) Y1.3
X2: C50.1 U7.26(X2) Y1.1
N16782838: R77.2 R78.2 U3.1(RESET#)
N16887406: R102.2 U7.12(\\~{WAKEUP})
N16916452: JP1.1 R122.1 U7.11(SCL)
N16916458: JP1.2 R100.2 R122.2 U8.6(SCL)
N16916991: R99.2 U7.10(SDA) U8.5(SDA)
N16919313: R94.1 U7.5(PUR)
N16919318: C45.1 R94.2 R96.1 U7.6(DP0)
N16919400: C49.2 R95.1 U7.7(DM0)
N16919998: R101.1 U7.1(\\~{VREGEN})
N16965307: R83.1 R120.1 U4.7(FSW)
N16965311: L1.1 U4.1(SW1) U4.2(SW2) U4.3(SW3)
N16965335: C34.1 U4.9(SS/TR)
N16968702: R98.2 U7.23(TEST0) U7.24(TEST1)
N16982334: R121.1 U8.7(WP)
N17024118: J13.2(DM) R95.2 U16.5(IO2)
N17024121: J13.3(DP) R96.2 U16.3(IO1)
N17075681: R131.1 U1.11(HPD_OUT)
N17076650: C61.1 J18.1
N17077181: JMP4.2 R132.1
N17077214: JMP4.3 R27.1
N17077452: JMP5.2 R133.1
N17077486: JMP5.3 R134.1
N17077740: JMP6.2 R135.1
N17077774: JMP6.3 R136.1
N17078062: JMP7.2 R137.1
N17078096: JMP7.3 R138.1
N17078348: JMP8.2 R139.1
N17078382: JMP8.3 R140.1
N17078649: JMP9.2 R141.1
N17078683: JMP9.3 R142.1
N17082573: J25.1 R150.1
N17083396: J27.1 R152.1
N17083699: JMP13.2 R154.1
N17083743: JMP13.3 R155.1
N17098810: D1.1(A) R82.1
N17100064: R168.2 U23.2(SCLA)
N17100067: R169.2 U23.3(SDAA)
N17100133: J31.3 R170.2
N17100137: J31.2 U23.5(EN)
N17100618: L7.4(2) R171.1 R183.2
N17100645: L7.1 R172.1 R184.2
N17100678: L3.4(2) R173.1 R185.2
N17100691: L3.1 R174.1 R186.2
N17100724: L4.4(2) R175.1 R187.2
N17100737: L4.1 R176.1 R188.2
N17100772: L5.4(2) R177.1 R189.2
N17100781: L5.1 R178.1 R190.2
N17106321: C64.1 J30.1
N17106522: J25.2 R182.1
N17107170: Q1.1(G) R5.2 R12.2
N17107194: Q1.3(D) Q2.1(G) R11.1
N17107221: Q2.3(D) R13.1
N17117344: J33.1 R194.1
N17130852: JMP16.2 R180.1
N17130854: JMP15.2 R204.1

Not connected (* = marked no-connect by the designer): D2 2*; J5 4(7)* 5(3)* 6(8)* 7(4)* 8(9)* 9(5)*; J13 4(ID)*; JMP4 1* 5*; JMP5 1* 5*; JMP6 1* 5*; JMP7 1* 5*; JMP8 1* 5*; JMP9 1* 5*; JMP13 1* 5*; U7 2(SUSP)* 13(\\~{CTS})* 14(\\~{DSR})* 15(\\~{DCD})* 16(\\~{RI}/CP)* 17(SIN/IR_SIN)* 19(SOUT/IR_SOUT)* 20(\\~{RTS})* 21(\\~{DTR})* 22(CLKOUT)* 31(P3_1)* 32(P3_0)*; U16 2(NC)*

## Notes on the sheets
sheet 2
- Pop C26 and depop
  R77 if not  using the
  Reset  SW.
sheet 3
- NOTES:
  - 100-ohm differential impedance for HDMI differential pairs.
- BLOCK DIAGRAM
- USB2
  CONNECTOR
- 5V
  DONGLE
- 5V to 3.3V
  LDO
- AARDVARK
  CONNECTOR
- TUSB3410
- SCL_CTL
- SDA_CTL
- HDMI CONNECTOR BOTTOM
- IN_D2P/N
- TMDS_D2P/N
- HDMI CONNECTOR
- IN_D1P/N
- TMDS_D1P/N
- TDP0604
  (40-pin WQFN)
- IN_D0P/N
- TMDS_D0P/N
- IN_CLKP/N
- TMDS_CLKP/N
- DDC_SCL/SDA
- DDC_SCL/SDA
- DDC - Snoop Only for TDP0604
sheet 4
- 3.3V BUCK REGULATOR - 4V to 17V input
sheet 5
- Pop R131, no pop R129, R130 for HPD on
  No pop R131, pop R129, R130 for HPD snoop only
- No pop R168 and R169 for TDP0604 DDC buffer enable
- Pop R168 and R169 for TDP0604 DDC buffer disable
  and TMDS1204
- Pop R165, R167, no pop R191 for TDP0604 DDC buffer enable
- No pop R165, R167, R191 for TDP0604 DDC buffer disable
- No pop R165, R167, pop R191 for TMDS1204
sheet 6
- HARDWARE AND ASSEMBLY NOTES
- Mounting Hole
- Mounting Hole
- Mounting Hole
- Mounting Hole
- PCB LOGO
  Texas Instruments
- PCB LOGO
  ESD1
- PCB LOGO
  FCC Disclaimer
- PCB LOGO
  CE LOGO
- PCB LOGO
  WEEE LOGO
- FIDUCIAL1
- FIDUCIAL2
- FIDUCIAL3
- FIDUCIAL4
- FIDUCIAL5
- FIDUCIAL6
- Install label in silkscreened box after final wash.
  Text shall be 8 pt font.  Text shall be per the Label
  Table in the PDF schematic.
- Variant / Label Table
- Variant
- Label Text
- 001
- TDP0604
sheet 7
- HDMI RX
- Pop R104 if U6 is no pop
  No pop R104 if U6 is pop
sheet 8
- HDMI TX
sheet 9
- AARDVARK
  CONNECTOR
- Pop R182 for TDP0604
  No pop R182 for TMDS1204
- 3.3V IO (DEFAULT)
- VIO must be set to 3.3V when using the Aardvark or the onboard TUSB3410 I2C controller.
